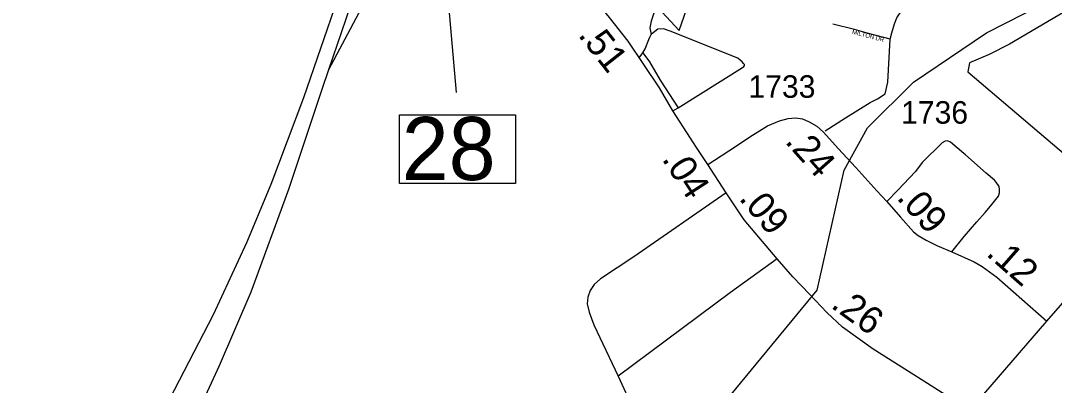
# Model space of a CAD drawing. Extents: x 2290615 to 2522933, y 819489 to 1012715.
# Drawn here: x 2396841 to 2402578, y 963963 to 965987 of the extents above; entities that cross this region are included whole.
import ezdxf

# ---------------------------------------------------------------- set-up
doc = ezdxf.new("R2010")
doc.units = 0
for name, color, linetype in [('Exist Boundary Political City Limit New', 7, 'Continuous'), ('Exist Hydrographic Misc Water Feature', 7, 'Continuous'), ('Exist Road Non-System Type 51', 7, 'Continuous'), ('Exist Road Primary Interstate Divided Center Attributed', 7, 'Continuous'), ('Exist Road Primary Interstate Ramp 1 Lane Attributed', 7, 'Continuous'), ('Exist Road Primary NC Attributed', 7, 'Continuous'), ('Exist Road Primary NC Mileage Hundredths English Label', 7, 'Continuous'), ('Exist Road Primary NC Structure Standard Bridge Number Label', 7, 'Continuous'), ('Exist Road Secondary Mileage Hundredths English Label', 7, 'Continuous'), ('Exist Road Secondary Type 51 Attributed', 7, 'Continuous'), ('Exist Road Secondary Type 51 Number Label', 7, 'Continuous'), ('Map Preparation Boundary City Limit Buffer Line', 7, 'Continuous')]:
    doc.layers.add(name, color=color, linetype=linetype)

msp = doc.modelspace()

# ---------------------------------------------------------------- linework, layer by layer
at = {"layer": 'Exist Boundary Political City Limit New'}
for points in [[(2401828.1, 974777.1), (2402082.3, 974670.9), (2401438.9, 973319.7), (2400923, 972312.7), (2400540.8, 971567), (2400082.2, 970356), (2400012.2, 970241.3), (2399821.1, 969674), (2399639.4, 968988.7), (2399541.5, 969007.9), (2399659.2, 969260.8), (2399441.1, 969349.1), (2399326.9, 969155.1), (2398980.7, 969285), (2398894.2, 969167.3), (2398542.8, 969279.8), (2398209.6, 969138.7), (2399316.1, 967384.2), (2399830.8, 966651.2), (2400496.2, 965932.8), (2401439.2, 968639.9)], [(2401439.2, 968639.9), (2402302.2, 968233), (2402152.3, 967778.7), (2402161.4, 967292.6), (2402256.8, 966502.1), (2402824.3, 966147.8), (2402329.4, 965857), (2402215.9, 965798), (2402106.9, 965752.5), (2402097.9, 965702.6), (2403001.3, 964934.8)]]:
    msp.add_lwpolyline(points, dxfattribs=at)
at = {"layer": 'Exist Hydrographic Misc Water Feature'}
msp.add_lwpolyline([(2400671.9, 963774.3), (2401262.8, 964491.3), (2401411.9, 965157.3), (2401541.9, 965392.4), (2401797, 965645.8), (2402202, 965918.5), (2402714.8, 966182.6), (2403003.9, 966378.3), (2403316.8, 966650.5), (2403590, 966812.7), (2403906, 966848.7), (2403955, 966932.7), (2403976.9, 967166.7), (2404058.9, 967285), (2404330.8, 967447.2), (2404430.9, 967457.9), (2404707.9, 967344.5), (2404765.9, 967343.6), (2404782.1, 967338.5)], dxfattribs=at)
at = {"layer": 'Exist Road Non-System Type 51'}
for p, q in [((2400274.1, 965779.8), (2400293.6, 965808.1)), ((2400461.5, 965485.8), (2400490.4, 965503.5)), ((2400461.5, 965485.8), (2400490.4, 965503.5))]:
    msp.add_line(p, q, dxfattribs=at)
for points in [[(2401001.7, 966738.8), (2400906.2, 966683.1), (2400831.8, 966657.8), (2400644.7, 966618), (2400611, 966600.5), (2400567.7, 966554.9), (2400519.9, 966465.9), (2400424.4, 966229.5), (2400375.3, 966090.1), (2400340.8, 965983.8), (2400334.1, 965946.7), (2400340.8, 965910.8)], [(2401667.8, 965883.1), (2401676.8, 965918.9), (2401691, 965969.8), (2401704.8, 966002.8), (2401723, 966030.2), (2401752.8, 966066.9), (2401797.8, 966116.8), (2401836.2, 966165.4), (2401853.8, 966195.6), (2401858.2, 966217.6)], [(2400490.4, 965503.5), (2400847.1, 965725.9), (2400855.2, 965733.1), (2400859.2, 965737.7), (2400859.2, 965742.9), (2400853.7, 965749.5), (2400846.3, 965757.8), (2400835, 965767.1), (2400821.9, 965777.7), (2400446.2, 965928.7), (2400408.5, 965940.8), (2400378.3, 965939.3), (2400361.9, 965927.2), (2400340.8, 965910.8)], [(2401667.8, 965883.2), (2401546.8, 965916.2), (2401469.2, 965938.2), (2401348.8, 965966.6)], [(2400293.6, 965808.1), (2400307.6, 965829.8), (2400327.5, 965882.9), (2400333.1, 965896), (2400340.8, 965910.8)], [(2401306.5, 965374.4), (2401419.8, 965447.8), (2401556.5, 965532.6), (2401597.2, 965553.1), (2401639.2, 965580.4), (2401654, 965645.7), (2401667.8, 965883.2)], [(2400293.6, 965808.1), (2400331.5, 965758), (2400390.4, 965656.8), (2400490.4, 965503.5)]]:
    msp.add_lwpolyline(points, dxfattribs=at)
at = {"layer": 'Exist Road Primary Interstate Divided Center Attributed'}
for points in [[(2399046.2, 967474.7), (2398942.8, 967142.4), (2398738, 966519.9), (2398599.5, 966108.2), (2398411.8, 965557.9), (2398229.2, 965078), (2398094.7, 964754.6), (2397910, 964355), (2397639, 963832.8), (2397458.3, 963515.5), (2397157.2, 963035.6), (2396976.6, 962766.5), (2396683.5, 962366.8), (2396390.4, 962003.3), (2395720.9, 961232.2), (2395013.4, 960412.8), (2394301.7, 959589.4), (2393725.6, 958880.5), (2393243.8, 958234.6)], [(2398551.4, 965715.1), (2398671.8, 966068), (2398800.3, 966453.6), (2398988.9, 967025.9), (2399112, 967374.5)], [(2391224.7, 954739.7), (2391718, 955661.7), (2392098.4, 956321.8), (2392303.8, 956641.7), (2392558.8, 957025.6), (2392812.9, 957379.2), (2393142, 957806.9), (2393503, 958244.7), (2393930.4, 958725.9), (2394528.6, 959404.7), (2395244.2, 960218), (2395945.8, 961013.3), (2396320.1, 961447), (2396737.7, 961985.3), (2396962.5, 962302.6), (2397189.3, 962656), (2397408.1, 963015.5), (2397616.9, 963399.1), (2397799.6, 963760.5), (2397944.1, 964073.8), (2398120.8, 964481.5), (2398329.5, 965051.8), (2398514.2, 965606.1), (2398551.4, 965715.1)]]:
    msp.add_lwpolyline(points, dxfattribs=at)
at = {"layer": 'Exist Road Primary Interstate Ramp 1 Lane Attributed'}
msp.add_lwpolyline([(2398551.4, 965715.1), (2398717.9, 966027.8), (2398941.1, 966314.1), (2399089.1, 966443.9), (2399232.2, 966549.9), (2399355.2, 966627.2), (2399506.9, 966721.7)], dxfattribs=at)
at = {"layer": 'Exist Road Primary NC Attributed'}
msp.add_line((2400756.9, 965030.8), (2400654.7, 965189), dxfattribs=at)
for points in [[(2400654.7, 965189), (2400592.3, 965282), (2400559.1, 965335.1), (2400461.5, 965485.8), (2400387.7, 965614.3), (2400212.3, 965872), (2400108.6, 966003.7), (2400021.3, 966114.9), (2399985.1, 966149.5), (2399795.9, 966340.9)], [(2401040.2, 964665.2), (2400857.2, 964881.1), (2400756.9, 965030.8)], [(2402103.7, 963819.1), (2402012.1, 963886.7), (2401798.6, 964021.9), (2401573.4, 964162.9), (2401403.4, 964285.1), (2401316.2, 964366.5), (2401221.1, 964466.8), (2401127.9, 964565.6), (2401040.2, 964665.2)]]:
    msp.add_lwpolyline(points, dxfattribs=at)
at = {"layer": 'Exist Road Primary NC Structure Standard Bridge Number Label'}
msp.add_line((2399119.5, 967163.9), (2399257.9, 965588.8), dxfattribs=at)
msp.add_lwpolyline([(2398944, 965464.8), (2399588.2, 965464.8), (2399588.2, 965082.5), (2398944, 965082.5)], close=True, dxfattribs=at)
at = {"layer": 'Exist Road Secondary Type 51 Attributed'}
for p, q in [((2402103.7, 963819.1), (2402537.3, 964319.9)), ((2400156.9, 964014.7), (2400364.7, 963562.6))]:
    msp.add_line(p, q, dxfattribs=at)
for points in [[(2402537.3, 964319.9), (2403005.8, 964854.6), (2403488.2, 965420.7), (2403698.9, 965659.6), (2403876.2, 965870), (2403958.1, 965973.2), (2404029.3, 966082), (2404046.8, 966118.5), (2404122.3, 966249.4)], [(2400654.7, 965189), (2400809.2, 965288.8), (2400887.7, 965342.6), (2400986.5, 965403.7), (2401053.3, 965431.3), (2401101.2, 965444.4), (2401141.9, 965447.3), (2401181.1, 965441.5), (2401217.5, 965425.5), (2401259.6, 965400.8), (2401297.4, 965368.8), (2401378.7, 965277.2), (2401476, 965171.1), (2401593.7, 965041.7), (2401648.2, 964983.2)], [(2402084.5, 965242), (2402076.4, 965249.4), (2402002.3, 965311.5), (2401984.9, 965319.2), (2401972.2, 965317.4), (2401955.1, 965309), (2401845.1, 965199.4), (2401807.3, 965150), (2401773.9, 965115.1), (2401709.9, 965045.3), (2401648.2, 964983.2)], [(2402009.2, 964703.7), (2402077.5, 964789.5), (2402148.7, 964869.4), (2402195.2, 964921.8), (2402224.2, 964956.7), (2402267.8, 965012.3), (2402273.6, 965031.2), (2402274.4, 965049.3), (2402271.5, 965066.8), (2402256.2, 965090.8), (2402246, 965102), (2402201, 965140.2), (2402084.5, 965242)], [(2400756.9, 965030.8), (2400244.1, 964675.4), (2400059.6, 964554), (2400024.7, 964522), (2400001.5, 964488.6), (2399988.4, 964452.2), (2399985.5, 964415.9), (2399995.7, 964369.4), (2400023.3, 964298.1), (2400156.9, 964014.7)], [(2401648.2, 964983.2), (2401724.5, 964897.1), (2401797.1, 964815.7), (2401821.8, 964793.8), (2401866.8, 964767.7), (2401929.3, 964737.2), (2402009.2, 964703.7)], [(2402009.2, 964703.7), (2402133.4, 964648.1), (2402178.5, 964621.9), (2402259.8, 964563.8), (2402537.3, 964319.9)], [(2401040.2, 964665.2), (2400781.6, 964477.7), (2400156.9, 964014.7)]]:
    msp.add_lwpolyline(points, dxfattribs=at)
at = {"layer": 'Map Preparation Boundary City Limit Buffer Line'}
for points in [[(2401828.1, 974777.1), (2402082.3, 974670.9), (2401438.9, 973319.7), (2400923, 972312.7), (2400540.8, 971567), (2400082.2, 970356), (2400012.2, 970241.3), (2399821.1, 969674), (2399639.4, 968988.7), (2399541.5, 969007.9), (2399659.2, 969260.8), (2399441.1, 969349.1), (2399326.9, 969155.1), (2398980.7, 969285), (2398894.2, 969167.3), (2398542.8, 969279.8), (2398209.6, 969138.7), (2399316.1, 967384.2), (2399830.8, 966651.2), (2400496.2, 965932.8), (2401439.2, 968639.9)], [(2401439.2, 968639.9), (2402302.2, 968233), (2402152.3, 967778.7), (2402161.4, 967292.6), (2402256.8, 966502.1), (2402824.3, 966147.8), (2402329.4, 965857), (2402215.9, 965798), (2402106.9, 965752.5), (2402097.9, 965702.6), (2403001.3, 964934.8)]]:
    msp.add_lwpolyline(points, dxfattribs=at)

# ---------------------------------------------------------------- texts
at = {"layer": 'Exist Boundary Political City Limit New'}
msp.add_text('  MILTON DR', height=24.017, rotation=345.35378, dxfattribs=at).set_placement((2401436, 965918.9))
at = {"layer": 'Exist Road Primary NC Mileage Hundredths English Label'}
for s, rotation, p in [('.51', 308.22043, (2399931.3, 965905.6)), ('.04', 302.87749, (2400397.2, 965218.9)), ('.09', 310.29647, (2400823.5, 964998)), ('.26', 324.30678, (2401332.4, 964397.7))]:
    msp.add_text(s, height=150, rotation=rotation, dxfattribs=at).set_placement(p)
at = {"layer": 'Exist Road Primary NC Structure Standard Bridge Number Label'}
msp.add_text('28', height=350, dxfattribs=at).set_placement((2398956.6, 965102.2))
at = {"layer": 'Exist Road Secondary Mileage Hundredths English Label'}
for s, rotation, p in [('.24', 311.61589, (2401079.2, 965313.2)), ('.09', 311.74267, (2401698.8, 965000.9)), ('.12', 318.69043, (2402194.9, 964687.4))]:
    msp.add_text(s, height=150, rotation=rotation, dxfattribs=at).set_placement(p)
at = {"layer": 'Exist Road Secondary Type 51 Number Label'}
for s, p in [('1733', (2400880.6, 965558.6)), ('1736', (2401727.8, 965415))]:
    msp.add_text(s, height=125, dxfattribs=at).set_placement(p)
at = {"layer": 'Map Preparation Boundary City Limit Buffer Line'}
msp.add_text('  MILTON DR', height=24.017, rotation=345.35378, dxfattribs=at).set_placement((2401436, 965918.9))

doc.saveas('drawing.dxf')
